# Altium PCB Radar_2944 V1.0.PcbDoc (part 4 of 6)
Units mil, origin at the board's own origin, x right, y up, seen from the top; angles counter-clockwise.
Board outline 3544.83 x 2556.65 mil, 8 copper layers (Top Layer, GND1, SIG1, PWR1, PWR2, SIG2, GND2, Bottom Layer), stack 55.2 mil thick; 301 components, 253 nets, 1055 pads, 1340 vias.
Unrouted connection lines stored in the file: 12.
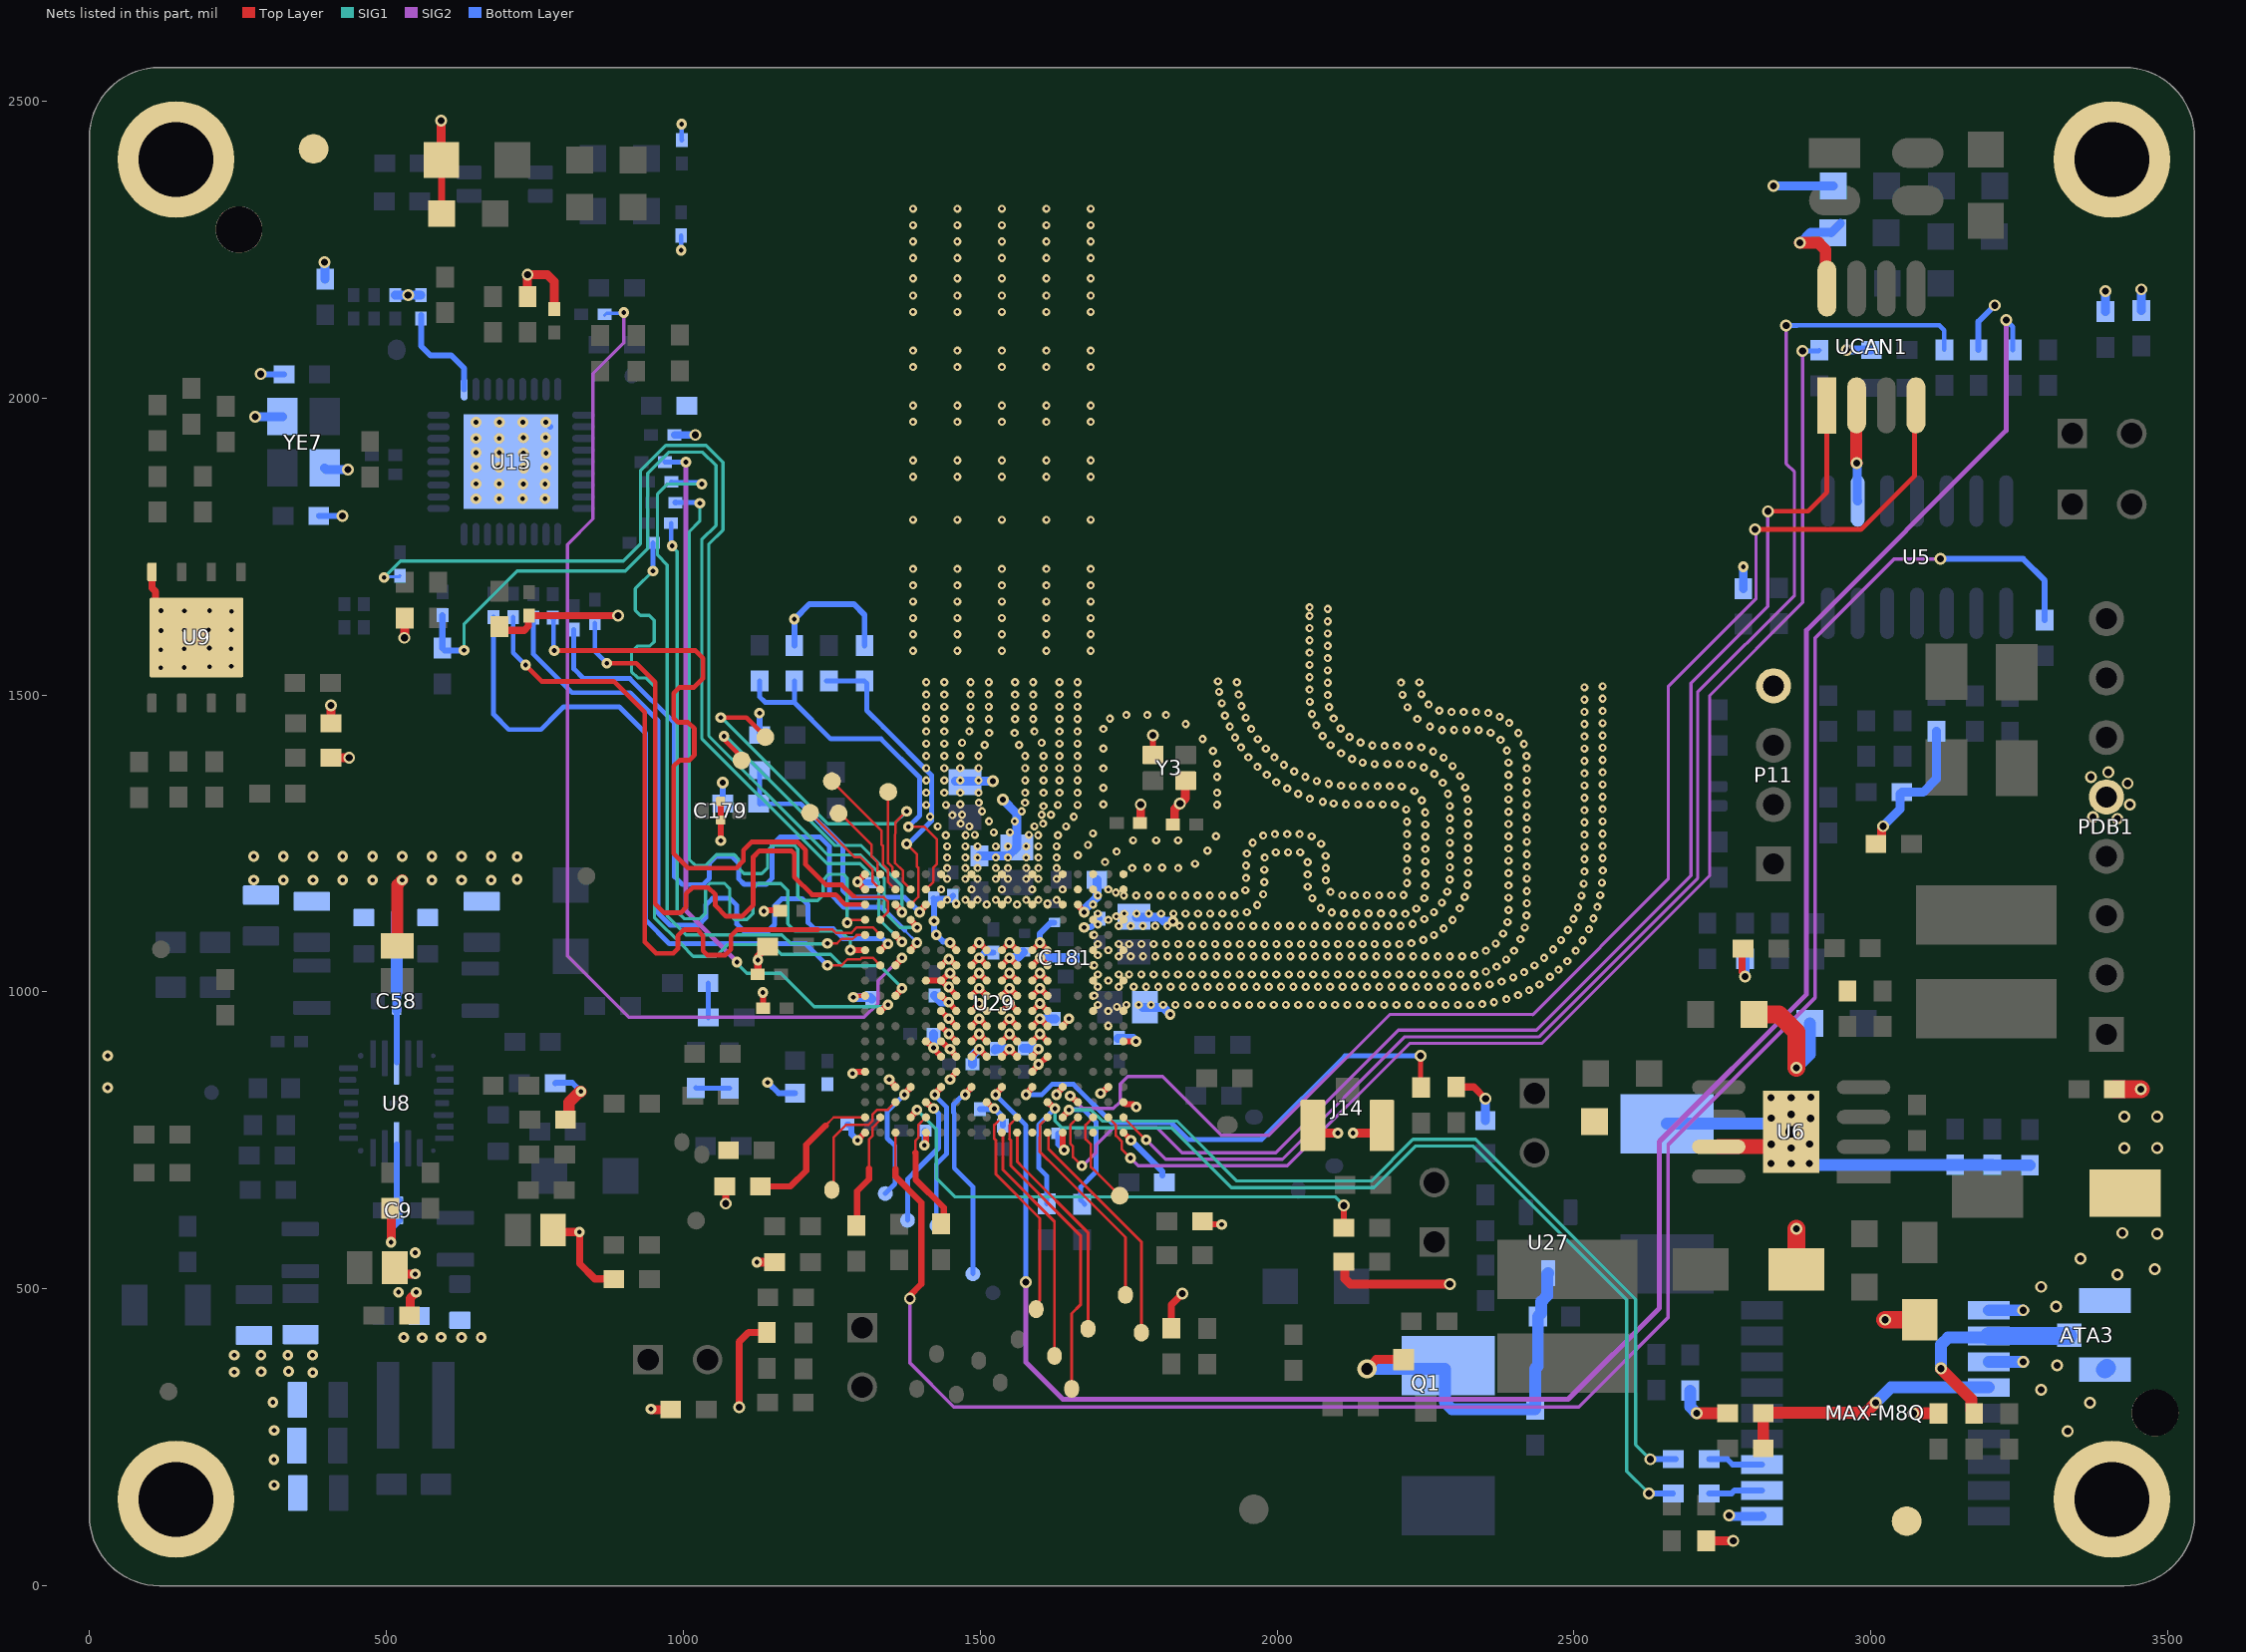
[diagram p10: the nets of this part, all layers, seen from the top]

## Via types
v1: diameter 13.77, hole 5.9, Top Layer to GND1, tented both sides, 427 vias
v2: diameter 18, hole 8, Top Layer to Bottom Layer, tented both sides, 341 vias
v3: diameter 13.77/13.77 (per signal layer), hole 5.9, Top Layer to GND1, tented both sides, 229 vias
v4: diameter 20, hole 12, Top Layer to Bottom Layer, tented both sides, 165 vias
v5: diameter 13.77, hole 5.9, Top Layer to GND1, tented top, 140 vias
v6: diameter 20, hole 10, Top Layer to Bottom Layer, tented both sides, 19 vias
v7: diameter 32, hole 20, Top Layer to Bottom Layer, tented both sides, 9 vias
v8: diameter 28, hole 16, Top Layer to Bottom Layer, tented both sides, 9 vias
v9: diameter 19.68, hole 7.87, Top Layer to Bottom Layer, tented both sides, 1 vias

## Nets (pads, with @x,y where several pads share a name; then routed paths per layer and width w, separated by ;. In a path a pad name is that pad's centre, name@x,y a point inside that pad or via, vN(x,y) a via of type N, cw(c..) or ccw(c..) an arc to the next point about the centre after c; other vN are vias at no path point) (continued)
GND: ATA3.2 C5.1 C6.1 C7.2 C8.1 C8G.2 C9.2 C11.1 C12.1 C13.1 C31.2 C32.2 C35.2 C40.2 C41.2 C44.2 C51.2 C52.2 C58.2 C80.2 C90.1 C91.1 C92.1 C95.2 C96.1 C102.2 C103.2 C105.1 C106.2 C107.1 C108.2 C110.2 C111.1 C112.2 C113.1 C114.2 C115.1 C116.2 C117.1 C120.2 C121.2 C125.2 C128.2 C129.2 C130.2 C131.1 C132.2 C134.2 C135.1 C136.1 C137.1 C138.1 C139.1 C140.1 C141.1 C142.1 C143.2 C144.1 C145.2 C146.1 C149.1 C150.1 C153.1 C163.1 C164.1 C165.1 C167.2 C168.1 C170.1 C172.1 C174.1 C175.1 C176.1 C177.1 C179.2 C180.2 C181.2 C199.2 C200.2 C201.2 C202.2 CBG1.2 CGP2.1 CN1.2 CP8.2 Cu1.2 Cu2.2 Cu3.1 Cu4.2 Cu5.2 Cu6.2 Cu7.2 D6.2 D8.A D12.2 D14.2 D15.2 D16.2 D17.2 J14.2 J14.3 MAX-M8Q.1 MAX-M8Q.10 MAX-M8Q.12 NT1.1 NT2.2 NT3.2 NT4.2 P11.4 pad. pad.38@377.56,2419.35 pad.38@3059.98,108.87 PDB1.5 Q1.2 R7.2 R57.1 R58.1 R79.1 R89.2 R102.2 R110.1 R172.1 R210.2 R251.1 R267.1 R282.1 R292.1 R312.1 R326.1 R335.1 R350.2 RCN3.2 RCN17.1 RCN18.1 RCN19.1 RG2.2 Rs303.1 TVS2.A U5.2 U6.0 U6.7 U8.12 U8.26 U9.4 U9.9 U15.37 U27.2 U29.A1 U29.A2 U29.A4 U29.A6 U29.A8 U29.A10 U29.A12 U29.A18 U29.B2 U29.B4 U29.B6 U29.B8 U29.B10 U29.B11 U29.C1 U29.C2 U29.C3 U29.C4 U29.C5 U29.C6 U29.C7 U29.C8 U29.C9 U29.C10 U29.D2 U29.D3 U29.E1 U29.E2 U29.E3 U29.E11 U29.E18 U29.F3 U29.F6 U29.F7 U29.F8 U29.F9 U29.F10 U29.F11 U29.F12 U29.F13 U29.G1 U29.G2 U29.G3 U29.G6 U29.G7 U29.G8 U29.G9 U29.G10 U29.G11 U29.G12 U29.G13 U29.G14 U29.H3 U29.H6 U29.H7 U29.H8 U29.H9 U29.H10 U29.H11 U29.H12 U29.H13 U29.J1 U29.J2 U29.J3 U29.J6 U29.J7 U29.J8 U29.J9 U29.J10 U29.J11 U29.J12 U29.J13 U29.K3 U29.K6 U29.K7 U29.K8 U29.K9 U29.K10 U29.K11 U29.K12 U29.K13 U29.K16 U29.L1 U29.L2 U29.L3 U29.L6 U29.L7 U29.L8 U29.L9 U29.L10 U29.L11 U29.L12 U29.L13 U29.M3 U29.M6 U29.M7 U29.M8 U29.M9 U29.M10 U29.M11 U29.M12 U29.M13 U29.M14 U29.N1 U29.N2 U29.N3 U29.N7 U29.N8 U29.N9 U29.N10 U29.N11 U29.N12 U29.N13 U29.P8 U29.P12 U29.P18 U29.V1 U29.V2 U29.V9 U29.V14 U29.V18 UCAN1.2 UCAN1.8 Y3.2 Y3.4 YE7.3 YE7.4 | length 9359.6
  Top Layer w4: v2(1446.97,929.47) 1453.36,923.07 U29.M12@1459.76,916.68 ; v2(1446.97,955.06) 1453.36,948.66 U29.M11@1459.76,942.27 ; U29.K16@1510.94,814.31 v2(1523.74,803.66)
  Top Layer w8: v2(1286.35,990.95) 1288.85,993.45 U29.V9@1306.22,993.45
  Top Layer w10: v2(1063.02,1254.47) C179.2@1063.02,1289.31 C179.2@1063.02,1320.81 ; C163.1@1134.19,968.26 v2(1134.19,999.11) ; v2(1135.76,1135.63) 1137.26,1137.13 C150.1@1163.92,1137.13 ; v2(1285.35,862.68) 1288.17,865.5 U29.V14@1306.22,865.5 ; v2(1293.42,750.34) U29.V18@1306.22,763.13 ; U29.V2@1306.22,1172.58 v2(1293.42,1185.38) U29.V1@1306.22,1198.17 ; v2(1406.08,741.68) 1408.58,744.18 U29.P18@1408.58,763.13 ; U29.P12@1408.58,916.68 v2(1421.38,906.02) U29.N13@1434.17,891.09 ; U29.P8@1408.58,1019.04 U29.N8@1434.17,1019.04 ; U29.N12@1434.17,916.68 v2(1449.11,903.88) 1455.58,896.11 U29.M13@1459.76,891.09 ; U29.N11@1434.17,942.27 v2(1446.97,929.47) 1453.36,923.07 U29.M12@1459.76,916.68 ; U29.N10@1434.17,967.86 v2(1446.97,955.06) 1453.36,948.66 U29.M11@1459.76,942.27 ; U29.N9@1434.17,993.45 1439.19,989.27 v2(1446.97,982.79) U29.M10@1459.76,967.86 ; U29.N7@1434.17,1044.63 v2(1446.97,1055.28) U29.M7@1459.76,1044.63 ; v2(1449.11,852.7) U29.M14@1459.76,865.5 ; v2(1449.11,1083.01) U29.M6@1459.76,1070.22 ; U29.M9@1459.76,993.45 v2(1446.97,1008.38) U29.N8@1434.17,1019.04 ; U29.M8@1459.76,1019.04 v2(1449.11,1031.83) U29.N8@1434.17,1019.04 ; U29.L13@1485.35,891.09 1490.04,895.77 v2(1498.15,903.88) U29.K13@1510.94,891.09 ; U29.L12@1485.35,916.68 1490.04,921.36 v2(1498.15,929.47) U29.K12@1510.94,916.68 ; U29.L11@1485.35,942.27 v2(1498.15,955.06) U29.K11@1510.94,942.27 ; U29.L10@1485.35,967.86 v2(1498.15,980.65) U29.K10@1510.94,967.86 ; U29.L9@1485.35,993.45 v2(1498.15,1006.24) U29.K9@1510.94,993.45 ; U29.L8@1485.35,1019.04 v2(1498.15,1031.83) U29.K8@1510.94,1019.04 ; U29.L7@1485.35,1044.63 v2(1498.15,1057.42) U29.K7@1510.94,1044.63 ; U29.L6@1485.35,1070.22 v2(1498.15,1083.01) U29.K6@1510.94,1070.22 ; U29.K16@1510.94,814.31 1515.96,810.13 v2(1523.74,803.66) ; U29.J13@1536.53,891.09 v2(1549.33,903.88) U29.H13@1562.12,891.09 ; U29.J12@1536.53,916.68 v2(1549.33,929.47) U29.H12@1562.12,916.68 ; U29.J11@1536.53,942.27 v2(1549.33,955.06) U29.H11@1562.12,942.27 ; U29.J10@1536.53,967.86 v2(1549.33,980.65) U29.H10@1562.12,967.86 ; U29.J9@1536.53,993.45 v2(1549.33,1006.24) U29.H9@1562.12,993.45 ; U29.J8@1536.53,1019.04 v2(1549.33,1031.83) U29.H8@1562.12,1019.04 ; U29.J7@1536.53,1044.63 v2(1549.33,1057.42) U29.H7@1562.12,1044.63 ; U29.J6@1536.53,1070.22 v2(1549.33,1083.01) U29.H6@1562.12,1070.22 ; U29.G14@1587.71,865.5 v2(1598.37,878.29) 1608.34,886.83 U29.F13@1613.31,891.09 ; U29.G13@1587.71,891.09 v2(1598.37,903.88) ; U29.G12@1587.71,916.68 v2(1600.51,929.47) U29.F12@1613.31,916.68 ; U29.G11@1587.71,942.27 v2(1600.51,955.06) U29.F11@1613.31,942.27 ; U29.G10@1587.71,967.86 v2(1600.51,980.65) U29.F10@1613.31,967.86 ; U29.G9@1587.71,993.45 v2(1600.51,1006.24) U29.F9@1613.31,993.45 ; U29.G8@1587.71,1019.04 v2(1600.51,1031.83) U29.F8@1613.31,1019.04 ; U29.G7@1587.71,1044.63 v2(1600.51,1057.42) U29.F7@1613.31,1044.63 ; U29.G6@1587.71,1070.22 v2(1600.51,1083.01) U29.F6@1613.31,1070.22 ; U29.E18@1638.9,763.13 1638.9,736.13 v2@1641.35,733.68 ; U29.E11@1638.9,942.27 v2(1649.55,955.06) ; U29.D3@1664.49,1146.99 1668.67,1141.97 v2(1675.14,1134.2) ; U29.A18@1741.26,763.13 v2(1754.05,750.34) ; U29.A12@1741.26,916.68 v2(1762.47,916.68) ; Y3.4@1791.04,1398.88 v4(1791.04,1432.13) ; R312.1@1874.45,613.76 1879.82,608.39 1906.74,608.39 v2(1906.79,608.34)
  Top Layer w12: U9.4@105.44,1706.9 105.44,1680.13 111.7,1673.87 111.7,1657.59 172.63,1596.66 U9.9@180.44,1596.66 ; C167.2@592.54,2400.68 593.31,2399.91 R282.1@593.31,2310.39 ; C32.2@690.45,1614.76 696.38,1608.83 732.42,1608.83 739.45,1615.86 739.45,1632.76 C35.2@740.45,1633.76 v4(890.35,1633.76) ; v2(825.42,595.72) 825.42,542.57 851.28,516.71 C105.1@883.25,516.71 ; R326.1@1069.9,672.54 1071.36,671.08 v4(1071.36,643.53) ; v4(1093.94,300.76) 1093.94,410.42 1109.88,426.35 RCN19.1@1140.74,426.35 ; C92.1@1125.41,1029.43 1125.41,1032.91 1125.77,1033.27 1125.77,1060.36 1130.7,1065.29 1130.7,1067.39 1139.7,1076.39 C137.1@1142.2,1076.39 ; D12.2@1821.7,433.66 1821.7,473.07 v4(1840.44,491.81) ; D6.2@2301.61,839.97 2331.08,839.97 2350.79,820.26 v4(2350.97,820.26) ; D14.2@2784.45,1072.76 2783.05,1071.36 2783.05,1033.3 2788.1,1028.25 v4(2788.1,1026.08)
  Top Layer w15: C91.1@406.8,1394.2 410.14,1390.86 413.73,1394.45 v4(437.51,1394.45) ; C90.1@407.07,1452.2 v4(407.07,1482.32) ; R210.2@506.71,635.6 508.1,634.21 v2(508.1,578.47) ; C31.2@514.12,535.76 524.88,525 v2(548.66,525) ; v4@530.71,1596.14 530.71,1629.32 R79.1@530.92,1629.53 ; C199.2@539.08,455.32 540.06,456.3 540.06,484.03 v2(550.42,494.39) ; C167.2@592.54,2400.68 v4(592.54,2466.92) ; C51.2@737.88,2170.52 v4(737.88,2207.77) 770.92,2207.77 782.71,2195.99 C52.2@782.71,2149.89 ; C120.2@780.65,599.09 784.03,595.72 v2(825.42,595.72) ; v2(945.78,297.69) 946.68,296.8 978.6,296.8 R267.1@978.72,296.92 ; v2(1124.01,544.94) 1153.93,544.94 RCN18.1@1154.01,544.86 ; C106.2@1769.32,1284.25 1770.29,1285.23 v4(1770.29,1315.34) ; C108.2@1827.19,1284.46 1827.19,1286.68 1827.31,1286.8 1827.31,1307.81 1845.62,1326.11 1845.62,1355.03 Y3.2@1846.16,1355.58 ; J14.2@2060.14,775.03 2072.77,762.4 v2(2102.13,762.4) ; R335.1@2112.6,545.76 2113.99,544.36 2113.99,517.04 2122.87,508.17 v4(2290.72,508.17) ; v2(2127.74,762.4) 2158.21,762.4 2163.12,757.49 2176.29,770.66 J14.3@2176.29,775.03 ; v7(2151.35,365.61) 2166.84,381.09 Q1.2@2212.97,381.09 ; v4(2706.41,290.69) v4@2706.61,290.49 ; D16.2@2722.45,75.85 v4(2768.09,75.85) ; Cu6.2@3008.21,1249.17 3010.71,1249.17 3018.21,1256.67 3018.21,1275.65 3020.09,1277.53 v4(3020.09,1278.89)
  Top Layer w20: C7.2@518.65,1077.45 518.65,1180.14 v2(526.76,1188.25) ; R102.2@801.64,785.1 802.66,785.1 807.66,790.1 807.66,814 825.91,832.25 v2(827.69,832.25) ; v4@2706.61,290.49 RG2.2@2758.54,290.49 ; v4(2880.37,2261) 2911.79,2261 2923.51,2249.28 UCAN1.8@2923.51,2186.51 ; UCAN1.2@2975.7,1987.46 2974.93,1986.68 2974.93,1891.21 v4(2975.95,1890.18) ; v4(3071.17,290.33) C8G.2@3113.7,290.33
  Top Layer w25: U6.7@2743.49,739.38 U6.0@2827.95,739.38
  Top Layer w30: R57.1@2803.04,962.05 2845.12,962.05 2874.46,932.71 v4(2874.46,872.46) ; U6.0@2827.95,739.38 v4(2831.97,743.39) ; D8.A@2874.46,532.95 v4(2874.46,601.23) ; v4(3023.81,448) TVS2.A@3082,448 ; Cu7.2@3410,836 v4@3454.36,836
  Bottom Layer w8: v2(996.49,2248.82) D15.2@996.49,2273.46 ; v2(997.14,2460.93) 997.14,2434.59 D17.2@997.69,2434.03
  Bottom Layer w8.3: v2@1135.76,1132.62 v2(1135.76,1135.63)
  Bottom Layer w10: v4(288.63,2040.24) 289.23,2039.65 C95.2@327.71,2039.65 ; C121.2@386.35,1801.51 386.45,1801.6 v4(426.05,1801.6) ; U8.12@517.53,743.44 517.53,650.84 C9.2@520.42,647.94 ; U8.26@517.53,881.24 C58.2@517.53,968.91 ; U15.37@729.64,1959.53 v2(730.08,1959.09) ; v2(767.37,1830.28) U15.37@770.54,1833.45 ; v2(768.43,1959.09) U15.37@775.96,1951.56 ; R292.1@784.35,846.19 785.14,846.99 812.96,846.99 v2(827.69,832.25) ; C136.1@1066.79,1319 v6(1066.79,1352.54) ; R172.1@1128.42,1432.58 v2(1128.42,1469.28) ; v2(1141.9,847.54) 1142.75,847.54 1160.87,829.42 C146.1@1188.42,829.42 ; C135.1@1187.05,1583.3 v2(1187.05,1627.5) 1212.34,1652.79 1287.57,1652.79 1305.32,1635.04 C131.1@1305.32,1583.4 ; C172.1@1276.7,776.47 1278.45,776.47 1283.29,771.63 1283.29,760.2 1293.15,750.34 v2(1293.42,750.34) ; v2(1293.42,1185.38) 1294.05,1184.75 1318.01,1184.75 C5.1@1318.64,1184.12 ; v2(1406.08,741.68) 1406.53,742.12 C177.1@1406.53,766.55 ; C113.1@1421.85,1157.38 1422.27,1156.96 1422.27,1119.53 v2(1422.22,1119.48) 1422.32,1119.37 1422.32,1102.14 v2@1426.16,1098.31 ; C113.1@1425.41,1153.82 1428.14,1156.55 1449.18,1156.55 1454.02,1161.39 C107.1@1454.02,1161.85 ; v2(1426.16,1096.14) 1437.76,1084.55 1447.58,1084.55 v2(1449.11,1083.01) ; v2(1498.15,1057.42) 1506.51,1065.79 C180.2@1522.24,1065.79 ; C165.1@1499.75,802.92 1523,802.92 v2(1523.74,803.66) 1538.03,789.37 C164.1@1538.03,775.02 ; v2(1600.51,1083.01) 1600.51,1098.34 1618.98,1116.81 C102.2@1624.94,1116.81 ; C181.2@1628.18,1057.19 C181.2@1659.68,1057.19 ; C170.1@1631.59,761.82 1631.59,743.44 v2@1641.35,733.68 ; v2(1675.14,1108.61) 1686.25,1108.61 C117.1@1700.89,1123.25 ; v2(1754.05,750.34) 1806.5,697.89 C175.1@1806.5,691.06 ; C12.1@3181.01,2081.08 3181.01,2128.56 v4(3208.37,2155.91)
  Bottom Layer w12: C44.2@985.3,1937.77 v4(1020.3,1937.77)
  Bottom Layer w15: v4(279.41,1968.6) YE7.4@325.25,1968.6 ; YE7.3@396.12,1881.99 398.8,1879.31 v4(435.63,1879.31) ; v4(396.12,2228.83) 396.63,2228.32 396.63,2200.5 R89.2@397.14,2199.99 ; v2(508.1,578.47) 508.1,604.12 C9.2@520.42,616.45 C9.2@520.42,647.94 ; R350.2@515.07,2173.04 v4(536.6,2173.04) 558.13,2173.04 R251.1@558.28,2173.18 ; C58.2@517.53,968.91 C58.2@517.53,1000.41 ; v2@824.85,596.29 v2(825.42,595.72) ; v2(1286.35,990.95) 1314.8,990.95 C174.1@1317.65,988.09 ; v2(1421.38,906.02) 1421.74,906.39 C138.1@1421.74,929.47 ; C139.1@1423.3,993.63 1434.13,982.79 v2(1446.97,982.79) ; C112.2@1458.48,1354.81 v6(1521.54,1354.81) ; C142.1@1487.01,878.09 1487.01,892.75 v2(1498.15,903.88) ; C115.1@1498.51,1228.9 1513.51,1228.9 1513.58,1228.96 1547.44,1228.96 C114.2@1561.59,1243.11 1561.59,1300.29 v6(1537.99,1323.9) ; C141.1@1524.6,902.58 C141.1@1525.9,903.88 v2(1549.33,903.88) ; v2(1549.33,1057.42) 1562.98,1057.42 C103.2@1572.83,1067.27 ; C140.1@1572.83,905.05 1597.2,905.05 v2(1598.37,903.88) ; v2(1600.51,955.06) 1601.17,954.4 C168.1@1626.1,954.4 ; v2(1600.51,1057.42) C181.2@1627.95,1057.42 ; C181.2@1628.18,1057.19 C181.2@1627.95,1057.42 ; C181.2@1659.68,1057.19 1659.44,1057.42 C181.2@1627.95,1057.42 ; v2(1675.14,1134.2) 1675.71,1134.77 1675.71,1138.51 1696.51,1159.31 C111.1@1696.51,1188.85 ; C176.1@1732.1,921.75 1757.39,921.75 v2(1762.47,916.68) ; C116.2@1762.74,1125.89 1802.12,1125.89 1808.9,1119.1 1824.02,1119.1 v2(1824.59,1118.53) ; C110.2@1773.84,973.96 1808.1,973.96 v2(1820.01,962.05) ; C149.1@2350.97,783.32 v4(2350.97,820.26) ; v4(2761.25,118.6) 2762.92,116.93 2815.85,116.93 MAX-M8Q.1@2816.39,117.47 ; Rs303.1@2785,1679 v2(2785,1715.75) ; v4(2788.1,1026.08) RCN17.1@2788.1,1055.75 ; v4(2835.48,2356.76) RCN3.2@2936.39,2356.76 ; v4(2880.37,2261) 2898.54,2279.17 2931.31,2279.17 2932.65,2277.83 CN1.2@2948.6,2293.79 ; v4(2959.01,2081.08) C11.1@3000.59,2081.08 ; v4(2975.95,1890.18) 2976.46,1889.67 2976.46,1827.47 U5.2@2977.45,1826.48 ; v4(3020.09,1278.89) 3048.83,1307.63 3048.83,1333.32 C13.1@3051.85,1336.34 3087.71,1336.34 3110.04,1358.67 C80.2@3110.04,1438.73 ; R110.1@3394.68,2145.28 v4(3394.68,2180.09) ; C128.2@3455.11,2147.27 v4(3455.11,2182.79)
  Bottom Layer w20: C58.2@517.53,1000.41 517.53,1131.77 ; v7(2151.35,365.61) 2282.76,365.61 2282.76,308.9 2294.47,297.18 Cu2.2@2434.59,297.18 2434.59,365.35 2439.17,369.93 C145.2@2439.17,453.52 2444.91,459.27 2444.91,478.58 2454.64,488.3 2454.64,524.76 U27.2@2456.45,526.57 ; CBG1.2@2656.45,777.98 2822.61,777.98 v4(2831.93,787.3) ; CGP2.1@2695.45,328.76 2695.45,301.66 v4(2706.41,290.69) ; v4(2874.46,872.46) 2896.93,894.93 R58.1@2896.93,946.76 ; v4(2896.61,743.79) 2896.61,720.85 2908.54,708.92 Cu4.2@3141.72,708.92 Cu1.2@3204.47,708.92 3205.14,708.24 Cu3.1@3267.55,708.24 ; MAX-M8Q.12@3198.28,377.31 v4(3256.07,377.31) ; MAX-M8Q.10@3198.28,463.92 v4(3256.07,463.92)
  Bottom Layer w30: ATA3.2@3393.91,364.15 ATA3.2@3397.02,367.27
  other v1: 1746.15,978.11 1766.82,978.11 1787.49,978.11 1808.16,978.11 1828.83,978.11 1849.5,978.11 1870.17,978.11 1890.84,978.11 1911.51,978.11 1932.18,978.11 1952.85,978.11 1973.52,978.11 1994.19,978.11 2014.86,978.11 2035.53,978.11 2056.2,978.11 2076.87,978.11 2097.54,978.11 2118.21,978.11 2138.88,978.11 2159.55,978.11 2180.22,978.11 2200.89,978.11 2221.56,978.11 2242.23,978.11 2262.9,978.11 2283.57,978.11 2304.24,978.11 2324.91,978.25 2345.54,979.61 2364.92,982.54 2386,987.94 2405.58,994.59 2424.35,1003.1 1758.62,1008.79 1779.29,1008.79 1799.96,1008.79 1820.63,1008.79 1841.3,1008.79 1861.97,1008.79 1882.64,1008.79 1903.31,1008.79 1923.98,1008.79 1944.65,1008.79 1965.32,1008.79 1985.99,1008.79 2006.66,1008.79 2027.33,1008.79 2048,1008.79 2068.67,1008.79 2089.34,1008.79 2110.01,1008.79 2130.68,1008.79 2151.35,1008.79 2172.02,1008.79 2192.69,1008.79 2213.36,1008.79 2234.03,1008.79 2254.7,1008.79 2275.37,1008.79 2296.04,1008.79 2316.71,1008.79 2337.36,1009.62 2357.83,1012.5 2441.6,1012.58 2377.91,1017.39 2397.42,1024.23 2459.32,1025.28 1750.67,1029.29 1771.34,1029.29 1792.01,1029.29 1812.68,1029.29 1833.35,1029.29 1854.02,1029.29 1874.69,1029.29 1895.36,1029.29 1916.03,1029.29 1936.7,1029.29 1957.37,1029.29 1978.04,1029.29 1998.71,1029.29 2019.38,1029.29 2040.05,1029.29 2060.72,1029.29 2081.39,1029.29 2102.06,1029.29 2122.73,1029.29 2143.4,1029.29 2164.07,1029.29 2184.74,1029.29 2205.41,1029.29 2226.08,1029.29 2246.75,1029.29 2267.42,1029.29 2288.09,1029.29 2308.76,1029.29 2331.63,1029.69 2415.96,1033.38 2351.47,1034.24 2473.8,1037.36 2369.48,1042.45 2433.39,1044.48 2488.56,1051.75 2385.63,1054.44 2449.65,1057.24 1753.54,1059.97 1774.21,1059.97 1794.88,1059.97 1815.55,1059.97 1836.22,1059.97 1856.89,1059.97 1877.56,1059.97 1898.23,1059.97 1918.9,1059.97 1939.57,1059.97 1960.24,1059.97 1980.91,1059.97 2001.58,1059.97 2022.25,1059.97 2042.92,1059.97 2063.59,1059.97 2084.26,1059.97 2104.93,1059.97 2125.6,1059.97 2146.27,1059.97 2166.94,1059.97 2187.61,1059.97 2208.28,1059.97 2228.95,1059.97 2249.62,1059.97 2270.29,1059.97 2290.96,1059.97 2311.63,1059.97 2332.22,1061.78 2351.47,1069.3 2398.82,1069.39 2502.74,1069.39 2464.57,1071.55 1750.86,1080.47 1771.53,1080.47 1792.2,1080.47 1812.88,1080.47 1833.55,1080.47 1854.22,1080.47 1874.89,1080.47 1895.56,1080.47 1916.23,1080.47 1936.9,1080.47 1957.57,1080.47 1978.24,1080.47 1998.91,1080.47 2019.57,1080.47 2040.24,1080.47 2060.91,1080.47 2081.59,1080.47 2102.26,1080.47 2122.93,1080.47 2143.6,1080.47 2164.27,1080.47 2184.94,1080.47 2205.61,1080.47 2368.2,1081.44 2226.13,1082.01 2514.22,1086.58 2246.18,1087.42 2478.01,1087.25 2409.87,1088.69 2264.12,1095.56 2380.36,1098.16 2489.49,1104.44 2524.98,1105.5 2280.25,1106.87 2416.94,1108.12 1753.36,1111.15 1774.03,1111.15 1794.7,1111.15 1815.37,1111.15 1836.04,1111.15 1856.71,1111.15 1877.38,1111.15 1898.05,1111.15 1918.72,1111.15 1939.39,1111.15 1960.06,1111.15 1980.73,1111.15 2001.4,1111.15 2022.07,1111.15 2042.74,1111.15 2063.41,1111.15 2084.08,1111.15 2104.75,1111.15 2125.42,1111.15 2146.09,1111.15 2166.76,1111.15 2187.43,1111.15 2208.1,1111.05 2228.31,1114.45 2387.9,1117.4 2295.29,1121.12 2247.65,1122.39 2499,1122.79 2532.6,1123.57 2420.04,1128.55 1742.6,1131.65 1763.27,1131.65 1783.94,1131.65 1804.61,1131.65 2264.17,1134.29 2389.73,1137.99 2234.39,1140.09 2307.47,1140.76 2506.66,1141.99 2539.25,1143.14 2420.4,1149.22 2277.46,1150.09 2389.73,1158.66 2315.71,1159.72 1741.91,1162.33 1762.58,1162.33 1783.25,1162.33 1803.92,1162.33 2512.39,1161.85 2544.15,1162.86 2286.38,1168.73 2420.4,1169.89 2389.73,1179.33 2320.33,1179.87 2516.13,1182.18 2546.79,1183.76 2290.48,1188.99 2420.4,1190.56 2321.55,1200.5 2389.73,1200 2517.48,1202.8 2548.14,1204.39 2290.88,1209.65 2420.4,1211.23 2389.73,1220.67 2321.55,1221.17 2517.4,1223.47 2548.08,1225.06 2290.88,1230.32 2420.4,1231.9 2389.73,1241.34 2321.55,1241.84 2517.4,1244.14 2548.08,1245.73 2073.99,1249.17 2290.88,1250.99 2420.4,1252.57 2321.55,1262.51 2389.73,1262.01 1491.19,1264.31 1581.88,1264.31 2517.4,1264.81 2548.08,1266.4 1522.94,1268.55 1550.13,1268.55 2290.88,1271.66 2420.4,1273.24 1481.87,1278.59 1591.2,1278.59 2389.73,1282.68 2321.55,1283.18 2517.4,1285.48 1514.88,1287.37 1558.19,1287.37 2548.08,1287.07 2290.88,1292.33 2420.4,1293.91 1469.6,1298.3 1603.46,1298.3 2389.73,1303.35 1503.07,1304.1 1570,1304.1 2321.55,1303.85 2517.4,1306.15 2548.08,1307.74 1606.54,1312.86 2291,1313 2420.4,1314.58 1466.53,1315.68 1497.67,1318.71 1575.4,1318.71 2320.64,1324.43 2389.73,1324.02 2517.4,1326.82 2548.08,1328.41 2287.52,1333.38 1466.53,1335.33 1497.21,1335.33 1575.86,1335.33 1606.54,1335.33 2420.4,1335.25 2230.96,1338.16 2316.79,1343.99 2389.73,1344.69 2517.4,1347.49 2548.08,1349.08 2278.88,1352.16 1466.53,1356 1497.21,1356 1575.86,1356 1606.54,1356 2420.4,1355.92 2308.25,1363.35 2389.73,1365.36 2264.47,1367.16 2517.4,1368.16 2548.08,1369.75 1466.53,1376.67 1497.21,1376.67 1575.86,1376.67 1606.54,1376.67 2420.4,1376.59 2247.14,1377.85 2295.29,1380.22 2226.92,1382.55 2164.27,1383.54 2185.77,1383.54 2206.44,1383.54 2144.03,1386.03 2389.73,1386.03 2517.4,1388.83 2548.08,1390.42 2126.03,1392.15 2280.25,1394.4 1466.53,1397.34 1497.21,1397.34 1575.86,1397.34 1606.54,1397.34 2420.04,1397.34 2107.62,1401.77 2262.58,1404.88 2386.83,1406.5 2517.4,1409.5 2242.88,1411.72 2548.08,1411.09 2180.87,1414.22 2201.54,1414.22 2222.21,1414.11 2090.06,1415.32 2160.21,1414.92 1507.62,1415.85 1565.44,1415.85 2415.36,1417.45 1469.6,1419.47 1603.46,1419.47 2140.42,1419.97 2376.27,1424.27 2121.91,1429.29 2517.4,1430.17 2076.51,1430.87 2548.08,1431.76 1515.18,1436.21 1557.89,1436.21 2359.51,1436.36 2406.1,1435.93 1439.67,1438.68 1481.87,1438.68 1591.2,1438.68 1633.4,1438.68 2297.97,1440.72 2318.64,1440.72 2339.31,1440.77 2277.46,1440.95 2106.77,1443.36 2257.32,1446.89 2065.93,1448.75 2517.4,1450.84 2548.08,1452.43 2390.72,1452.9 1483.79,1459.35 1514.47,1459.35 1558.6,1459.35 1589.27,1459.35 2236.14,1459.59 2095.14,1460.39 2374.85,1463.29 2058.6,1467.84 2355.5,1469.6 2293.57,1471.39 2314.24,1471.39 2334.91,1471.39 2517.4,1471.51 2273.03,1473.77 2548.08,1473.1 2087.65,1479.45 2219.68,1479.15 1483.79,1480.02 1514.47,1480.02 1558.6,1480.02 1589.27,1480.02 2255.11,1484.06 2055.12,1488.52 2517.4,1492.18 2548.08,1493.77 1483.79,1500.69 1514.47,1500.69 1558.6,1500.69 1589.27,1500.69 2085.24,1499.99 2211.08,1500.08 2243.13,1500.9 2054.57,1509.17 2517.4,1512.85 2548.08,1514.44 2085.24,1520.66 1483.79,1521.36 1514.47,1521.36 1558.6,1521.36 1589.27,1521.36 2208.71,1520.95 2239.53,1521.26 2054.57,1529.84 2085.24,1541.33 2054.57,1550.51 2085.24,1562 2054.57,1571.18 2085.24,1582.67 2054.57,1591.85 2085.24,1603.34 2054.57,1612.52 2085.24,1624.01 2054.57,1633.19 2085.24,1644.68 2054.55,1647.6
  other v2: 311.19,169.58 310.7,212.61 311.19,261.5 309.23,308.93 376.05,358.92 244.13,359.99 289.17,360.52 335.54,361.32 244.15,388.25 289.15,388.25 334.15,388.25 375.63,388.34 529.3,418.27 560.57,417.94 592.5,418.6 626.74,418.27 659.68,418.27 520.42,494.39 548.66,561.02 1641.25,733.68 30.69,838.54 30.69,892.36 1125.77,1053.61 276.76,1188.25 326.76,1188.25 376.76,1188.25 426.76,1188.25 476.76,1188.25 576.76,1188.25 626.76,1188.25 676.76,1188.25 720.35,1189.64 720.35,1227.55 276.76,1228.25 326.76,1228.25 376.76,1228.25 426.76,1228.25 476.76,1228.25 526.76,1228.25 576.76,1228.25 626.76,1228.25 676.76,1228.25 120.35,1545.78 159.62,1546.22 202.66,1547.65 238.89,1548.21 120.34,1576.12 159.83,1577.69 238.61,1577.7 202.1,1579.1 120.79,1608.24 159.62,1608.74 200.98,1609.71 239.17,1609.71 239.58,1640.76 120.55,1641.67 160.04,1641.5 202.38,1641.73 650.9,1830.28 690.27,1830.28 729.64,1830.28 650.9,1855.45 690.27,1855.45 730.6,1855.12 767.37,1854.92 731.04,1881.99 768.46,1882.17 650.9,1883.24 690.27,1883.24 730.65,1906.99 769.09,1906.97 650.9,1907.89 690.27,1907.89 650.9,1931.88 690.27,1931.88 730.64,1932.93 768.21,1933.47 650.9,1959.09 690.38,1959.09
  other v3: 1715.49,943.55 1715.67,967.87 1730.28,974.76 1697.96,978.09 1692.24,993.91 1697.96,1008.8 1733.39,1008.79 1715.67,1019.05 1697.96,1029.27 1733.39,1029.29 1692.01,1044.79 1733.39,1059.97 1697.96,1061.78 1715.67,1070.23 1697.96,1080.45 1733.39,1080.47 1692.01,1096 1733.39,1111.15 1697.96,1113.68 1715.67,1121.41 1729.29,1127.26 1697.96,1131.63 1510.94,1146.99 1562.12,1146.99 1690.08,1146.99 1459.76,1148.88 1613.43,1148.88 1444.41,1154.87 1475.12,1154.87 1495.59,1154.87 1526.3,1154.87 1546.77,1154.87 1577.48,1154.87 1597.96,1154.87 1628.67,1154.87 1697.96,1162.34 1728.48,1167.28 1434.17,1172.58 1485.34,1172.58 1536.52,1172.58 1587.7,1172.58 1638.89,1172.58 1715.67,1172.58 1444.42,1190.3 1475.1,1190.3 1495.6,1190.3 1526.28,1190.3 1546.78,1190.3 1577.46,1190.3 1597.97,1190.3 1628.65,1190.3 1444.42,1208.69 1475.1,1208.69 1495.6,1208.69 1526.28,1208.69 1546.79,1208.69 1577.46,1208.69 1597.97,1208.69 1628.64,1208.69 1444.42,1226.36 1475.1,1226.36 1495.6,1226.36 1526.28,1226.36 1546.79,1226.36 1577.46,1226.36 1597.97,1226.36 1628.64,1226.36 1444.42,1245.03 1475.1,1245.03 1495.6,1245.03 1526.28,1245.03 1546.79,1245.03 1577.46,1245.03 1597.97,1245.03 1628.64,1245.03 1442.23,1263.75 1475.3,1263.66 1597.77,1263.66 1630.83,1263.75 1428.38,1278.59 1644.68,1278.59 1467.05,1283.38 1606.02,1283.38 1415.66,1294.88 1657.41,1294.88 1453.36,1297.57 1619.21,1298.3 1408.99,1314.61 1442.44,1314.67 1630.63,1314.67 1664.09,1314.61 1408.99,1335.33 1439.67,1335.33 1633.4,1335.33 1664.08,1335.33 1408.99,1356 1439.67,1356 1633.4,1356 1664.08,1356 1408.99,1376.67 1439.67,1376.67 1633.4,1376.67 1664.08,1376.67 1408.99,1397.34 1439.67,1397.34 1633.4,1397.34 1664.08,1397.34 1408.99,1418.01 1439.67,1418.01 1633.4,1418.01 1664.08,1418.01 1408.99,1438.68 1664.08,1438.68 1408.99,1459.35 1439.67,1459.35 1633.4,1459.35 1664.08,1459.35 1408.99,1480.02 1439.67,1480.02 1633.4,1480.02 1664.08,1480.02 1408.99,1500.69 1439.67,1500.69 1633.4,1500.69 1664.08,1500.69 1408.99,1521.36 1439.67,1521.36 1633.4,1521.36 1664.08,1521.36 1386.93,1574.35 1461.73,1574.35 1536.53,1574.35 1611.34,1574.35 1686.14,1574.35 1386.93,1601.91 1461.73,1601.91 1536.53,1601.91 1611.34,1601.91 1686.14,1601.91 1386.93,1629.47 1461.73,1629.47 1536.53,1629.47 1611.34,1629.47 1686.14,1629.47 1386.93,1657.03 1461.73,1657.03 1536.53,1657.03 1611.34,1657.03 1686.14,1657.03 1386.93,1684.59 1461.73,1684.59 1536.53,1684.59 1611.34,1684.59 1686.14,1684.59 1386.93,1712.15 1461.73,1712.15 1536.53,1712.15 1611.34,1712.15 1686.14,1712.15 1386.93,1794.82 1461.73,1794.82 1536.53,1794.82 1611.34,1794.82 1686.14,1794.82 1386.93,1867.3 1461.73,1867.3 1536.53,1867.3 1611.34,1867.3 1686.14,1867.3 1386.93,1894.86 1461.73,1894.86 1536.53,1894.86 1611.34,1894.86 1686.14,1894.86 1386.93,1959.78 1461.73,1959.78 1536.53,1959.78 1611.34,1959.78 1686.14,1959.78 1386.93,1987.34 1461.73,1987.34 1536.53,1987.34 1611.34,1987.34 1686.14,1987.34 1386.93,2052.26 1461.73,2052.26 1536.53,2052.26 1611.34,2052.26 1686.14,2052.26 1386.93,2079.82 1461.73,2079.82 1536.53,2079.82 1611.34,2079.82 1686.14,2079.82 1386.93,2144.75 1461.73,2144.75 1536.53,2144.75 1611.34,2144.75 1686.14,2144.75 1386.93,2172.3 1461.73,2172.3 1536.53,2172.3 1611.34,2172.3 1686.14,2172.3 1386.93,2201.37 1461.73,2201.37 1536.53,2201.37 1611.34,2201.37 1686.14,2201.37 1386.93,2235.77 1461.73,2235.77 1536.53,2235.77 1611.34,2235.77 1686.14,2235.77 1386.93,2263.33 1461.73,2263.33 1536.53,2263.33 1611.34,2263.33 1686.14,2263.33 1386.93,2290.89 1461.73,2290.89 1536.53,2290.89 1611.34,2290.89 1686.14,2290.89 1386.93,2318.45 1461.73,2318.45 1536.53,2318.45 1611.34,2318.45 1686.14,2318.45
  other v4: 3331.22,260.46 3368.7,308.13 3286.6,330.22 3313.35,371.16 3311.82,470.03 3286.6,503.38 3414.66,523.72 3477.89,533.37 3352.78,550.6 3481.67,593.01 3423.14,594.11 2831.37,711.26 2865.52,711.03 2896.29,711.03 2865.46,737.01 3426.74,737.01 3481.67,737.24 2898.38,787.12 3426.74,789.73 3481.67,789.73 2865.46,793.88 2831.48,822.15 2865.53,822.15 2898.93,822.71 3454.36,836.16 3414.66,1291.43 3373.47,1294.56 3435.78,1315.47 1836.46,1316.96 3432.02,1351.02 3370.33,1361.89 3399.4,1369.63 530.56,1596.14
  other v5: 1825.28,1131.65 1845.95,1131.65 1866.62,1131.65 1887.29,1131.65 1907.96,1131.65 1928.63,1131.65 2215.98,1131.46 2112.65,1131.98 2133.32,1131.98 2153.99,1131.98 2174.66,1131.98 2195.33,1131.98 2092.04,1133.63 1949.06,1134.18 2073.62,1141.34 1966.26,1146.32 2059.24,1157.64 2247.82,1157.75 1824.59,1162.33 1845.26,1162.33 1865.93,1162.33 1886.6,1162.33 1907.27,1162.33 1927.94,1162.33 2109.63,1162.66 2130.3,1162.66 2150.97,1162.66 2171.64,1162.66 2192.31,1162.66 2212.97,1163.2 1976.4,1164.33 2089.79,1168.47 1946.63,1171.16 2051.33,1177.12 2249.38,1178.54 2218.7,1183.06 1978.33,1184.91 2082.01,1187.62 1947.66,1191.81 2051.33,1197.77 2249.38,1199.21 2218.7,1203.73 1978.33,1205.58 1755.99,1208.62 1833.55,1208.62 2082.01,1208.29 1781.79,1209.09 1806.33,1209.09 1947.66,1212.48 1861.83,1215.55 1710.26,1218.69 2051.33,1218.44 2249.38,1219.88 2218.7,1224.4 1978.9,1226.25 2081.59,1229.21 1664.49,1230.28 1949.06,1233.1 1997.63,1235 2018.3,1235 2038.97,1235 1729.77,1236.32 1882.64,1237.74 2249.38,1240.55 2218.7,1245.07 1681.51,1247.44 1958.74,1251.36 1757.31,1255.07 1796.39,1255.07 1833.35,1255.07 2058.13,1261.74 2249.38,1261.22 1897.1,1262.01 1976.4,1263.31 1996.4,1265.68 2017.07,1265.68 2037.74,1265.68 2218.7,1265.74 1690.08,1266.87 2249.38,1281.89 2218.7,1286.41 2249.18,1302.56 2217.29,1307.04 1707.41,1315.68 1898.89,1315.05 2136.44,1315.54 2157.11,1315.54 2177.78,1315.54 2198.45,1315.54 2115.77,1315.86 2095.14,1317.21 2076.87,1320.16 2243.65,1322.48 2055.12,1325.4 2035.41,1333.41 1898.89,1335.33 2016.88,1342.55 1707.41,1343.48 2127.58,1346.49 2148.53,1346.21 2169.2,1346.21 2189.87,1346.21 2210.2,1345.86 2107.54,1347.25 2087.04,1350.11 1998.71,1352.94 2066.81,1354.91 1898.89,1361.91 2047.45,1361.91 1982.55,1365.53 2028.81,1371.07 1707.41,1376.59 1967.01,1379.15 2011.54,1382.13 1898.89,1384.45 1951.57,1394.97 1995.4,1395.12 1892.03,1405.71 1707.41,1409.7 1980.77,1409.57 1939.28,1411.72 1967.62,1425.58 1874.69,1425.94 1929.26,1428.19 1707.41,1442.8 1956.21,1442.84 1920.11,1446.73 1846.16,1450.93 1718.61,1460.21 1947.13,1461.58 1911.94,1465.34 1746.18,1466.36 1781.49,1466.36 1812.88,1466.36 1940.2,1481.08 1906.69,1485.8 1935.19,1500.8 1902.36,1505.29 1932.1,1521.48 1900.33,1522.87
GPADC1: C136.2 R316.1 U29.P3 | length 463
  Top Layer w10.6: v2(1397.93,1134.2) 1404.4,1141.97 1406.91,1144.98 U29.P3@1408.58,1146.99
  Bottom Layer w8.3: R316.1@1128.51,1373.6 1128.51,1316.28 1128.9,1316.67 1197.86,1316.67 1268.75,1245.78 1268.75,1170.8 1280.41,1159.14 1372.98,1159.14 v2(1397.93,1134.2)
GPADC2: C135.2 R315.1 U29.P2 | length 628
  Top Layer w4.19: v2(1379.35,1277.9) 1406.32,1277.9 1427.25,1256.98 1427.25,1215.22 1421.38,1209.35 1421.38,1185.38 U29.P2@1408.58,1172.58
  Bottom Layer w8.3: R315.1@1128.42,1523.52 1128.42,1497.04 1138.08,1487.37 1187.05,1487.37 ; C135.2@1187.05,1523.3 1187.05,1487.37 ; v2(1379.35,1277.9) 1397.93,1296.48 1397.93,1361.35 1333.29,1425.98 1248.43,1425.98 1187.05,1487.37
GPADC3: C131.2 R133.1 U29.R3 | length 519.5
  Top Layer w4.19: v2(1376.35,1249.22) 1393.26,1232.31 1393.26,1211.42 1395.79,1208.9 1395.79,1159.79 U29.R3@1382.99,1146.99
  Bottom Layer w8.3: R133.1@1241.32,1523.4 C131.2@1305.32,1523.4 1309.01,1519.71 1309.01,1473.74 1336.92,1445.83 1418.08,1364.67 1418.08,1287.98 1379.31,1249.22 v2(1376.35,1249.22)
GPADC4: pad.27@1138.23,1429.02 U29.R2 | length 632.1
  Top Layer w4.19: v2(1376.35,1304.27) 1357.04,1284.95 1356.85,1247.39 1356.85,1216.83 1370.2,1203.49 1370.2,1185.38 U29.R2@1382.99,1172.58
  Top Layer w8: v2(1063.1,1462.02) 1106.27,1462.02 pad.27@1139.86,1428.43
  SIG1 w5.5: v2@1067.23,1459.39 1243.47,1283.16 1355.24,1283.16 v2(1376.35,1304.27)
GPADC5: pad.27@1098.23,1389.9 U29.T3 | length 514.7
  Top Layer w8: v2(1068.81,1430.42) 1068.81,1424.76 1092.95,1400.62 pad.27@1092.95,1389.9
  Top Layer w10.6: U29.T3@1357.4,1146.99 1361.58,1141.97 v2(1368.05,1134.2)
  SIG1 w5.5: v2(1068.81,1430.42) 1071.19,1430.42 1253.15,1248.46 1255.05,1246.56 1299.44,1246.56 1368.05,1177.95 v2(1368.05,1134.2)
GPADC6: pad.27@1213.58,1301.68 U29.U2 | length 183.9
  Top Layer w4.19: pad.27@1213.58,1301.68 1266.8,1248.46 1288.1,1227.16 1298.08,1227.16 1319.01,1206.23 1319.01,1185.38 U29.U2@1331.81,1172.58
GPADC7: pad.30 U29.T1 | length 143.7
  Top Layer w4.19: pad.30@1345.16,1336.79 1345.16,1217.07 1352.71,1209.52 1352.71,1202.86 U29.T1@1357.4,1198.17
GPADC8: pad.29 U29.T2 | length 226.6
  Top Layer w4.19: pad.29@1250.37,1354.81 1333.47,1271.71 1333.47,1248.46 1336.02,1245.91 1336.02,1214.77 1344.62,1206.17 1344.62,1204.83 1344.61,1185.38 U29.T2@1357.4,1172.58
GPADC9: pad.28 U29.U1 | length 133.2
  Top Layer w4.19: pad.28@1261.42,1300.51 1264.35,1300.51 1316.4,1248.46 1317.14,1247.72 1317.14,1228.04 1327.19,1217.99 1327.19,1202.79 U29.U1@1331.81,1198.17
GPIO_3: pad.8@1377.67,615.52 U29.P16 | length 230
  Top Layer w10.6: U29.P16@1408.58,814.31 1413.6,810.13 v2(1421.38,803.66)
  Bottom Layer w8.3: pad.8@1377.67,615.52 1377.67,684.83 1395.52,702.68 1429.93,737.09 1429.93,795.11 v2(1421.38,803.66)
GPIO_4: pad.5 U29.L15 | length 341.6
  Top Layer w10.6: v2(1474.7,827.11) 1481.17,834.88 U29.L15@1485.35,839.9
  Bottom Layer w8.3: v2(1474.7,827.11) 1472.07,827.11 1467.22,822.26 1466.9,822.26 1455.41,810.76 1455.41,796.56 1456.34,795.62 1456.34,703.2 1487.63,671.91 pad.5@1487.63,525.26
GPIO_8: R233.1 U29.T18 | length 3553.6
  Top Layer w4.19: 1357.4,701.93 U29.T18@1357.4,763.13
  Top Layer w10.6: 1357.4,701.93 1357.4,689.28 1401.19,645.49 1401.19,508.17 1381.71,488.68 v4(1381.71,483.54)
  SIG2 w6: v4(1381.71,483.54) 1381.71,375.35 1455.66,301.4 2507.85,301.4 2658.57,452.12 2658.57,743.14 2906.11,990.68 2906.11,1595.94 3039.24,1729.06 v4(3117.1,1729.06)
  Bottom Layer w10: v4(3117.1,1729.06) 3255.94,1729.06 3292.55,1692.45 R233.1@3292.55,1625.91
GPIO_9: pad.8@1427.21,606.44 U29.N15 | length 252.6
  Top Layer w10.6: v2(1423.52,827.11) 1429.99,834.88 U29.N15@1434.17,839.9
  Bottom Layer w8.3: v2(1423.52,827.11) 1423.52,825.77 1443.11,806.18 1443.11,726.79 1426.16,709.84 1426.16,702.68 pad.8@1426.16,606.31
GPIO_30: R23.2 U29.P17 | length 208.2
  Top Layer w4.19: 1390.99,728.97 1390.99,749.47 1395.79,754.27 1395.79,775.93 U29.P17@1408.58,788.72
  Top Layer w10.6: 1390.99,728.97 1391.31,728.65 1391.31,683.93 1438.62,636.61 1438.62,613.94 R23.2@1434.1,609.42
GPIO_31: R22.2 U29.U17 | length 198.7
  Top Layer w4.19: 1312.63,702.68 1312.63,751.45 1319.01,757.83 1319.01,771.76 1331.81,784.56 U29.U17@1331.81,788.72
  Top Layer w10.6: R22.2@1291.45,606.76 1292.59,607.9 1292.59,664.79 1312.63,684.83 1312.63,702.68
"GPS RF_ATA": ATA3.1 L11.2 MAX-M8Q.11 | length 361.6
  Top Layer w20: v4(3117.97,365.84) 3117.97,364.97 3168.64,314.3 3168.64,295.33 L11.2@3173.64,290.33
  Bottom Layer w20: v4(3117.97,365.84) 3117.97,406.42 3129.69,418.14 3195.8,418.14 MAX-M8Q.11@3198.28,420.61 ; ATA3.1@3332.26,420.61 ATA3.1@3333.87,422.22
  Bottom Layer w30: MAX-M8Q.11@3198.28,420.61 ATA3.1@3332.26,420.61
GRXD: MAX-M8Q.3 RGP2.1 | length 93.1
  Bottom Layer w10: RGP2.1@2727.19,213.41 2757.69,213.41 2767.02,204.08 MAX-M8Q.3@2816.39,204.08
GTXD: MAX-M8Q.2 RGP1.1 | length 91.4
  Bottom Layer w10: RGP1.1@2727.19,155.54 2764.97,155.54 2770.2,160.77 MAX-M8Q.2@2816.39,160.77
INH: R251.2 U15.10 | length 175.2
  Bottom Layer w10: R251.2@558.42,2139.21 558.42,2087.55 574.39,2071.57 609.35,2071.57 631.22,2049.71 U15.10@631.22,2014.6
LNA: MAX-M8Q.13 RG1.1 RG2.1 | length 456.7
  Top Layer w20: RG1.1@2818.54,231.54 RG2.1@2818.54,290.49 2819.83,291.79 2991.18,291.79 v4(3007.52,308.13)
  Bottom Layer w20: v4(3007.52,308.13) 3033.39,334 MAX-M8Q.13@3198.28,334
LVDS_TX0_N: pad.4 U29.F18 | length 402.1
  Top Layer w5: U29.F18@1613.43,763.01 1614.99,761.45 1614.99,735.48 1647.79,702.68 1771.34,579.12 pad.4@1771.34,426.3
LVDS_TX0_P: pad.3 U29.F17 | length 363.8
  Top Layer w4: 1600.51,755.72 1600.51,775.93 U29.F17@1613.31,788.72
  Top Layer w5: 1600.51,755.72 1600.51,730.84 1628.68,702.68 1690.83,640.52 1744.56,586.79 pad.3@1744.56,489.86
LVDS_TX1_N: pad.16@1625.09,387.22 U29.J18 | length 412.6
  Top Layer w5: U29.J18@1536.53,763.13 1538.21,761.45 1538.21,756.04 1538.44,755.81 1538.44,702.68 1538.44,700.14 1625.09,613.49 pad.16@1625.09,387.22
LVDS_TX1_P: pad.16@1594.14,465.85 U29.J17 | length 358.3
  Top Layer w4: 1523.74,752.87 1523.74,775.93 U29.J17@1536.53,788.72
  Top Layer w5: 1523.74,752.87 1526.44,750.17 1526.44,730.67 1526.27,730.5 1526.27,692.94 1600.51,618.7 1600.51,480.13 1597.97,477.59 1597.97,472.33 pad.16@1600.51,469.79
LVDS_TX2_CLK_N: U29.G18
LVDS_TX2_CLK_P: U29.G17
LVDS_TX3_FRCLK_N: pad.15 U29.H18 | length 379.8
  Top Layer w5: U29.H18@1562.12,763.13 1562.37,762.89 1562.37,713.94 1573.63,702.68 1681.51,594.8 pad.15@1681.51,432.75
LVDS_TX3_FRCLK_P: pad.34 U29.H17 | length 528.3
  Top Layer w4: 1549.33,752.28 1549.33,775.93 U29.H17@1562.12,788.72
  Top Layer w5: 1549.33,752.28 1551.93,749.69 1551.93,706.86 1556.11,702.68 1668.75,590.04 1668.75,473.07 1654.08,458.4 pad.34@1654.08,321.26
MCU_CLK_OUT: pad.9 U29.R15 | length 207.6
  Top Layer w10.6: v2(1372.34,827.11) 1378.81,834.88 U29.R15@1382.99,839.9
  Bottom Layer w8.3: pad.9@1340.25,660.47 1356.54,676.77 1356.54,740.74 1343.3,753.98 1343.3,798.07 v2(1372.34,827.11)
MSS_EPWMA0: U29.E15 | length 16.7
  Top Layer w10.6: v2(1628.24,827.11) 1634.72,834.88 U29.E15@1638.9,839.9
MSS_EPWMA1: U29.C18
MSS_EPWMB0: pad.2 U29.C17 | length 150.8
  Top Layer w4.19: U29.C17@1690.08,788.72 1677.28,775.93 1677.28,751.94 1686.54,742.68 1686.54,705.15 1689.01,702.68 pad.2@1727.63,664.06
MSS_GPIO_0: U29.B15 | length 16.6
  Top Layer w10.6: v2(1702.87,829.25) 1710.65,835.72 U29.B15@1715.67,839.9
MSS_GPIO_1: U29.A16 | length 24.8
  Top Layer w10.6: U29.A16@1741.26,814.31 1744.56,811.01 1757.9,811.01 v2(1762.74,806.18)
MSS_GPIO_2: R347.2 U29.G15 | length 838.3
  Top Layer w8.3: v4(2241.76,892.17) 2241.76,839.52 R347.2@2242.09,839.19
  Top Layer w10.6: v2(1577.06,827.11) 1583.54,834.88 U29.G15@1587.71,839.9
  Bottom Layer w8.3: v2(1577.06,827.11) 1603.99,827.11 1621.14,844.26 1657.25,844.26 1721.53,779.98 1821.36,779.98 1849.92,751.43 1973.48,751.43 2114.23,892.17 v4(2241.76,892.17)
MSS_GPIO_11: R54.1 U29.J15 | length 3605.2
  Top Layer w10.6: v2(1525.88,827.11) 1532.35,834.88 U29.J15@1536.53,839.9
  SIG2 w8.3: v4(1577.09,511.17) 1577.09,376.14 1639.18,314.05 2489.88,314.05 2643.42,467.6 2643.42,747.96 2891.29,995.83 2891.29,1608.86 3227.45,1945.02 v4@3227.45,2131.73
  Bottom Layer w8.3: v2(1525.88,827.11) 1525.88,826.37 1577.09,775.16 v4(1577.09,511.17) ; v4(3227.45,2130.98) 3238.92,2119.51 R54.1@3238.92,2081.08
MSS_GPIO_28: R334.2 U29.R17 | length 888.3
  Top Layer w5.5: R334.2@2112.45,602.76 R334.2@2112.54,602.85
  Top Layer w10: R334.2@2112.54,602.85 v4(2112.54,640.3)
  Top Layer w10.6: U29.R17@1382.99,788.72 1387.17,793.74 v2(1393.64,801.52)
  SIG1 w5.5: v2(1393.64,801.52) 1426.39,768.78 1426.39,686.1 1457.44,655.04 2097.8,655.04 v4(2112.54,640.3)
MSS_I2CA_SCL: R3.1 R276.1 | length 59.7
  Bottom Layer w8.3: R276.1@1041.73,1015.17 1042.53,1014.37 R3.1@1042.53,955.85
MSS_I2CA_SDA: R31.1 R277.1 | length 57.3
  Bottom Layer w8.3: R277.1@1021.31,838.39 1021.8,837.9 R31.1@1078.46,837.9
MSS_MCANA_RX: U29.D16 UCAN1.4 | length 2393.9
  Top Layer w8: v4(2804.52,1778.65) 2983.17,1778.65 3073.31,1868.79 UCAN1.4@3073.31,2013.6
  Top Layer w10.6: v2(1651.69,824.97) 1659.47,818.49 U29.D16@1664.49,814.31
  SIG2 w5.5: v2(1651.69,824.97) 1673,803.66 1724.4,803.66 1735.76,815.03 1735.76,845.21 1748.16,857.6 1807.4,857.6 1906.28,758.73 1986.29,758.73 2189.6,962.05 2430.43,962.05 ; 2430.43,961.46 2658.57,1189.59 2658.57,1513.67 2806.21,1661.31 2806.21,1776.96 v4(2804.52,1778.65)
MSS_MCANA_TX: U29.D17 UCAN1.1 | length 2317.4
  Top Layer w4.19: U29.D17@1664.49,788.72 1651.69,775.93 1651.69,744.58 1656.35,739.93 1656.35,734.23 1656.35,721.72 1670.94,707.13 v2(1671.35,707.13)
  Top Layer w8: v4(2826.55,1809.23) 2893.79,1809.23 2925.7,1841.14 UCAN1.1@2925.7,1987.46 UCAN1.1@2925.7,2012.89
  SIG2 w5.5: v2(1671.35,707.13) 1672.93,707.13 1694.92,729.12 1694.92,741.97 1724.59,771.64 1797.11,771.64 1839.62,729.12 1997.96,729.12 2204.23,935.4 2436.78,935.4 2697.04,1195.65 2697.04,1519.78 2826.1,1648.83 v4@2826.1,1809.38
MSS_MCANB_RX: R25.1 U29.A17 | length 2499.4
  Top Layer w4.19: U29.A17@1741.26,788.72 1779.31,750.68 v2(1779.31,750.85)
  SIG2 w5.5: v2(1779.31,750.85) 1812.04,718.12 2009.04,718.12 2215.31,924.4 2441.34,924.4 2708.04,1191.1 2708.04,1504.54 2871.12,1667.62 2871.12,1875.35 2857.04,1889.43 v4(2857.04,2122.13)
  Bottom Layer w8: v4(2857.04,2122.13) 2875.12,2122.13 2875.35,2122.35 3115.04,2122.35 3123.36,2114.03 R25.1@3123.36,2081.08
MSS_MCANB_TX: R21.1 U29.B17 | length 2243.8
  Top Layer w4.19: U29.B17@1715.67,788.72 1728.46,775.93 1728.46,757.83 1735.96,750.34 ; 1735.98,750.34 1738.55,747.77 1738.55,734.7 v2(1753.04,720.2)
  SIG2 w5.5: v2(1753.04,720.2) 1764.5,708.74 1766.11,707.13 1838.16,707.13 ccw(c1838.58,718.12) 1838.58,707.13 2016.87,707.12 2223.15,913.4 2445.9,913.4 2728.32,1195.82 2728.32,1499.02 2884.72,1655.43 v4(2884.72,2079.16)
  Bottom Layer w8: v4(2884.72,2079.16) 2911.61,2079.16 R21.1@2912.77,2080.32
MSS_MDIO_CLK: R249.1 U29.R4 | length 1778.7
  Top Layer w10.6: U29.R4@1382.99,1121.4 1387.17,1116.38 v2(1393.64,1108.61)
  SIG1 w5.5: v2(496.23,1697.81) 523.87,1725.44 899.1,1725.44 927.94,1754.28 927.94,1877.2 970.7,1919.96 1038.25,1919.96 1066.83,1891.38 1066.83,1777.78 1043.04,1754 1043.04,1431.09 1227.35,1246.78 1243.61,1230.52 1298.86,1230.52 1338.54,1190.84 1338.54,1134.53 1364.46,1108.61 v2(1393.64,1108.61)
  Bottom Layer w5.5: v2(496.23,1697.81) 496.78,1697.81 497.87,1698.9 521.37,1698.9 R249.1@523.28,1700.81
MSS_MDIO_DATA: R247.1 R280.1 U29.T5 | length 1765.7
  Top Layer w10.6: U29.T5@1357.4,1095.81 1357.4,1094.95 v2(1368.05,1084.3)
  SIG1 w5.5: v2(630.98,1575.03) 630.98,1619.77 719.99,1708.78 902.5,1708.78 940.13,1746.41 940.13,1873.08 975.67,1908.62 1032.91,1908.62 1055.2,1886.32 1055.2,1785.34 1031.19,1761.33 1031.19,1426.99 1227.35,1230.82 1242.15,1216.02 1298.13,1216.02 1329.14,1185.01 1329.14,1123.21 v2(1368.05,1084.3)
  Bottom Layer w10: R280.1@594.45,1578.76 598.17,1575.03 v2(630.98,1575.03)
  Bottom Layer w10.6: R280.1@594.45,1578.76 594.68,1578.99 R247.1@594.68,1634
MSS_RGMII_RCLK: R234.1 U29.T9 | length 1216.7
  Top Layer w10.6: U29.T9@1357.4,993.45 1361.58,998.47 v2(1368.05,1006.24)
  SIG1 w5.5: v2(949.04,1708.78) 919.16,1678.9 919.16,1642.61 927.94,1633.83 942.79,1633.83 951.08,1625.54 951.08,1589.47 943.99,1582.39 923.43,1582.39 912.87,1571.83 912.87,1539.41 923.59,1528.68 937.23,1528.68 951.48,1514.43 951.48,1125.15 996.98,1079.64 1016.88,1059.75 1055.12,1059.75 1075.01,1079.64 1148.8,1079.64 1165.16,1063.28 1248.06,1063.28 1267.23,1044.12 1331.14,1044.12 1368.05,1007.21 v2(1368.05,1006.24)
  Bottom Layer w8: v2(949.04,1708.78) 949.04,1711.66 R234.1@949.06,1756.18
MSS_RGMII_RCTL: R245.1 U29.T7 | length 1842.5
  Top Layer w10.6: U29.T7@1357.4,1044.63 1361.58,1049.65 v2(1368.05,1057.42)
  SIG2 w5.5: v2(899.73,2143.7) 899.73,2092.89 848,2041.16 848,1796.33 805.08,1753.41 805.08,1060.77 908.4,957.45 1220.52,957.45 1227.35,957.45 1281.89,957.45 1304.84,957.45 1327.8,980.41 1327.8,1018.38 1366.85,1057.42 v2(1368.05,1057.42)
  Bottom Layer w5.5: R245.1@867.45,2138.76 871.13,2142.44 898.48,2142.44 v2(899.73,2143.7)
MSS_RGMII_RD0: R237.1 U29.V6 | length 1218.3
  Top Layer w10.6: v2(1281.2,1070.23) 1299.6,1070.22 U29.V6@1306.22,1070.22
  SIG1 w5.5: v2(981.25,1751.12) 981.25,1750.15 989.75,1741.65 989.75,1134.75 1001.17,1123.32 1028,1123.32 1037.77,1133.09 1037.77,1175.45 1045.09,1182.77 1069.33,1182.77 1078.2,1173.9 1078.2,1129.77 1085.88,1122.08 1107.2,1122.08 1117.2,1132.09 1117.2,1173.4 1126.11,1182.31 1164.62,1182.31 1176.16,1170.77 1176.16,1114.72 1188.78,1102.1 1265.79,1102.1 1281.2,1086.68 v2(1281.2,1070.23)
  Bottom Layer w8: R237.1@979.53,1789.15 979.53,1755.02 981.25,1753.31 v2(981.25,1751.12)
MSS_RGMII_RD1: R238.1 U29.V4 | length 1205.1
  Top Layer w4.19: v2(1276.12,1116.32) 1281.2,1121.4 U29.V4@1306.22,1121.4
  SIG1 w5.5: v2(1027.81,1822.75) 1027.81,1792.39 1010.28,1774.85 1010.28,1561.79 1010.17,1561.67 1010.17,1423.26 1010.28,1423.15 1010.28,1222.85 1020.48,1212.65 1037.5,1212.65 1056.04,1231.19 1086,1231.19 1093.35,1223.83 1093.35,1208.26 1102.31,1199.3 1132.03,1199.3 1142.17,1209.45 1142.17,1238.27 1150.62,1246.72 1186.71,1246.72 1192.96,1240.47 1192.96,1161.26 1200.17,1154.05 1226.74,1154.05 1235.52,1162.83 1235.52,1188.46 1245.13,1198.08 1269.74,1198.08 1276.12,1191.69 v2(1276.12,1116.32)
  Bottom Layer w8: R238.1@987.28,1823.93 v2@1019.93,1823.93
  Bottom Layer w10: R238.1@987.05,1823.71 R238.1@987.28,1823.93
MSS_RGMII_RD2: R239.1 U29.V5 | length 1210.1
  Top Layer w4.19: v2(1242.6,1081.63) 1258.93,1081.63 1266.48,1089.18 1285.42,1089.18 1292.05,1095.81 U29.V5@1306.22,1095.81
  SIG1 w5.5: v2(1031.19,1854.92) 973.16,1854.92 956.63,1838.4 956.63,1735.12 973,1718.75 973,1128.16 1005.02,1096.14 1166.31,1096.14 1181.58,1080.87 1241.84,1080.87 v2(1242.6,1081.63)
  Bottom Layer w8: R239.1@980.05,1858.71 981.33,1857.43 1025.97,1857.43 1028.48,1854.92 v2(1031.19,1854.92)
MSS_RGMII_RD3: R240.1 U29.U10 | length 1217.3
  Top Layer w10.6: U29.U10@1331.81,967.86 1336.83,972.04 v2(1344.6,978.51)
  SIG1 w5.5: v2(1090.3,1050.36) 1090.3,1048.13 1107.16,1031.27 1164.48,1031.27 1220.55,975.2 1335.13,975.2 1336.05,976.12 1342.21,976.12 v2(1344.6,978.51)
  SIG2 w8: v2(1004.51,1891.87) 1004.51,1136.14 v2(1090.3,1050.36)
  Bottom Layer w8: R240.1@969.02,1891.87 v2(1004.51,1891.87)
MSS_RGMII_TCLK: R74.1 U29.V3 | length 1118.8
  Top Layer w8: v2(871.27,1553.24) 920.55,1553.24 952.74,1521.05 952.74,1148.21 967.83,1133.12 995.21,1133.12 1005.02,1142.94 1005.02,1165.3 1015.55,1175.82 1042.09,1175.82 1054.1,1163.81 1054.1,1145.35 1072.19,1127.26 1098.66,1127.26 1117.83,1146.43 1117.83,1227.28 1128.06,1237.52 1182.3,1237.52 1186.99,1232.83 1186.99,1193.39 1216.84,1163.54 1227.35,1163.54 1256.4,1163.54 1272.95,1146.99 U29.V3@1306.22,1146.99
  Bottom Layer w8: R74.1@851.32,1621.09 851.32,1573.19 v2(871.27,1553.24)
MSS_RGMII_TCTL: R230.1 U29.R6 | length 1216.6
  Top Layer w10.6: U29.R6@1382.99,1070.22 1387.17,1075.24 v2(1393.64,1083.01)
  Bottom Layer w4: 1373.1,1103.56 v2(1393.64,1083.01)
  Bottom Layer w8.3: R230.1@815.77,1609.74 815.77,1543.98 832.33,1527.43 910.29,1527.43 985.3,1452.42 985.3,1193.98 998.59,1180.69 1033.59,1180.69 1043.97,1191.06 1043.97,1216.56 1055.37,1227.97 1082.1,1227.97 1093.65,1216.42 1093.65,1190.14 1102.64,1181.15 1139.88,1181.15 1149.48,1190.76 1149.48,1247 1163.02,1260.55 1230.5,1260.55 1246.45,1244.6 1246.45,1166.45 1270.33,1142.57 1334.09,1142.57 1373.1,1103.56
MSS_RGMII_TD0: R96.1 U29.U7 | length 1216.4
  Top Layer w4.19: v2(1242.6,1044.62) 1266.22,1044.62 1276.74,1055.13 1298.63,1055.13 1300.92,1057.42 1319.01,1057.42 U29.U7@1331.81,1044.63
  Bottom Layer w8.3: R96.1@680.42,1631.02 680.42,1467.66 706.32,1441.76 760.41,1441.76 789.43,1470.78 798.51,1479.86 892.36,1479.86 936.8,1435.41 936.8,1120.9 976.84,1080.87 1206.35,1080.87 v2(1242.6,1044.62)
MSS_RGMII_TD1: R100.1 U29.U5 | length 1218.5
  Top Layer w4.19: 1227.35,1104.78 1251.54,1104.78 1253.46,1102.85 1257.09,1099.22 1283.21,1099.22 1292.59,1108.61 1319.01,1108.61 U29.U5@1331.81,1095.81
  Top Layer w8: v2(734.41,1550.26) 761.8,1522.87 883.08,1522.87 935.14,1470.8 935.14,1083.96 954.12,1064.99 983.36,1064.99 990.89,1072.52 990.89,1094.02 1001.65,1104.78 1023.1,1104.78 1033.36,1094.52 1033.36,1069.16 1040.4,1062.11 1070.89,1062.11 1080.49,1071.72 1080.49,1094.35 1090.92,1104.78 1227.35,1104.78
  Bottom Layer w8: R100.1@713.42,1631.02 713.42,1571.25 v2(734.41,1550.26)
MSS_RGMII_TD2: R178.1 U29.U6 | length 1216.8
  Top Layer w10.6: U29.U6@1331.81,1070.22 1336.83,1074.4 v2(1344.6,1080.87)
  Bottom Layer w8.3: R178.1@747.42,1630.39 747.42,1569.08 812.67,1503.84 910.41,1503.84 957.83,1456.41 957.83,1132.53 978.02,1112.34 1025.53,1112.34 1038.3,1125.11 1038.3,1146.67 1049.03,1157.4 1078.51,1157.4 1090.3,1145.62 1090.3,1114.15 1102.31,1102.14 1142.8,1102.14 1153.91,1113.25 1153.91,1144.77 1165.93,1156.79 1200.26,1156.79 1210.41,1146.64 1210.41,1116.66 1220.96,1106.11 1252.72,1106.11 1269.05,1089.78 1335.7,1089.78 v2(1344.6,1080.87)
MSS_RGMII_TD3: R225.1 U29.U4 | length 1217.7
  Top Layer w4.19: 1285.67,1161.49 1287.36,1159.8 1296.72,1159.8 ; 1296.74,1159.79 1337.11,1159.79 1344.6,1152.29 1344.6,1134.2 U29.U4@1331.81,1121.4
  Top Layer w8: v2(782.72,1574.88) 1020.18,1574.88 1033.36,1561.7 1033.36,1527.81 1018.28,1512.73 993.77,1512.73 983.94,1502.9 983.94,1461.15 991.42,1453.67 1008.26,1453.67 1018.88,1443.04 1018.88,1398.82 1010.15,1390.08 993.88,1390.08 983.94,1380.13 983.94,1232.69 1008.08,1208.54 1089.27,1208.54 1101.52,1220.79 1101.52,1238.78 1115.26,1252.52 1192.24,1252.52 1205.96,1238.8 1205.96,1214.62 1227.35,1193.23 1240.36,1180.22 1266.94,1180.22 1285.67,1161.49 1287.36,1161.49
  Bottom Layer w8: v2@781.43,1578.81 R225.1@781.43,1629.37
  Bottom Layer w10.6: R225.1@780.42,1630.39 R225.1@781.43,1629.37 ; v2@781.43,1578.81 782.72,1577.52 v2(782.72,1574.88)
MSS_RS232RX: R278.1 RGP1.2 U29.F16 | length 1744.9
  Top Layer w10.6: U29.F16@1613.31,814.31 1618.33,810.13 v2(1626.1,803.66)
  SIG1 w5.5: v2(1626.1,803.66) 1626.1,782.63 1637.75,770.98 1822.39,770.98 1922.79,670.59 2163.35,670.59 2233.44,740.68 2329.51,740.68 2588.66,481.52 2588.66,192.87 v4(2625.99,155.54)
  SIG2 w5.5: v2@1624.75,802.31 v2(1626.1,803.66)
  Bottom Layer w8.3: R278.1@1612.22,642.98 1612.22,689.93 1598.37,703.78 1598.37,775.93 v2(1626.1,803.66)
  Bottom Layer w10: v4(2625.99,155.54) RGP1.2@2666.63,155.54
MSS_RS232TX: R279.1 RGP2.2 U29.E17 | length 1691.6
  Top Layer w10.6: U29.E17@1638.9,788.72 1643.08,793.74 v2(1649.55,801.52)
  SIG1 w5.5: v2(1649.55,801.52) 1686.44,801.52 1705.32,782.63 1831.12,782.63 1932.17,681.59 2158.72,681.59 2228.81,751.68 2334.07,751.68 2603.69,482.05 2603.69,237.59 v4(2628.23,213.05)
  Bottom Layer w8.3: v2(1649.55,801.52) 1674.36,801.52 1694.92,780.96 1694.92,696.78 1669.47,671.34 1669.47,649.23 R279.1@1676.11,642.6
  Bottom Layer w10: v4@2625.49,213.41 RGP2.2@2667.19,213.41 RGP2.2@2671.23,213.41
MSS_SPIA_CLK: pad.31 U29.T16 | length 223.2
  Top Layer w4.19: pad.31@1253.64,666.76 1253.64,755.47 1274.09,775.93 1311.74,775.93 1319.01,783.2 1319.01,794.02 1326.51,801.52 1344.58,801.52 ; 1344.59,801.5 U29.T16@1357.4,814.31
MSS_SPIA_CS0: U29.T15 | length 16.6
  Top Layer w10.6: v2(1346.75,852.7) 1353.22,844.92 U29.T15@1357.4,839.9
MSS_SPIA_HOSTIRQ: R326.2 U29.V17 | length 249.9
  Top Layer w4.19: 1239.64,775.03 1253.33,788.72 U29.V17@1306.22,788.72
  Top Layer w10.6: R326.2@1129.9,672.54 1180.56,672.54 1207.23,699.21 1207.23,742.62 1239.64,775.03
MSS_SPIA_MISO: R392.1 | length 7.4
  Top Layer w10.6: R392.1@1070.9,738.55 R392.1@1076.13,733.32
